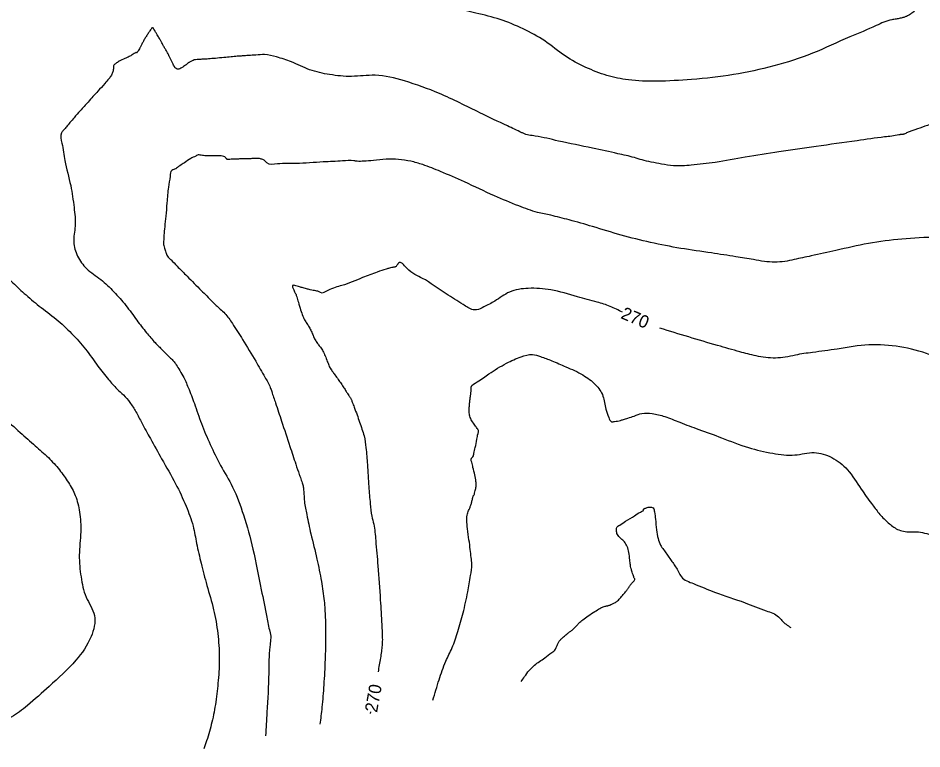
# Model space of a CAD drawing. Extents: x -475575 to -473225, y -1116053 to -1114104.
# Drawn here: x -474761.3 to -474473.3, y -1116036.6 to -1115803.6 of the extents above; entities that cross this region are included whole.
import ezdxf

# ---------------------------------------------------------------- set-up
doc = ezdxf.new("R2010")
doc.units = 0
for name, color, linetype in [('Vrstevnice_hlavni', 7, 'Continuous'), ('Vrstevnice_popis', 7, 'Continuous'), ('Vrstevnice_vedlejsi', 7, 'Continuous')]:
    doc.layers.add(name, color=color, linetype=linetype)

msp = doc.modelspace()

# ---------------------------------------------------------------- linework, layer by layer
at = {"layer": 'Vrstevnice_hlavni'}
msp.add_line((-474648.99, -1116025.33), (-474648.89, -1116024.79), dxfattribs=at)
for points in [[(-474568.71, -1115897.41), (-474572.64, -1115895.54), (-474576.77, -1115894.2), (-474583.07, -1115892.45), (-474591.54, -1115890.28), (-474598.74, -1115889.8), (-474604.7, -1115890.98), (-474609.4, -1115893.85), (-474612.89, -1115895.74), (-474615.18, -1115896.66), (-474616.27, -1115896.61), (-474619.51, -1115894.92), (-474624.89, -1115891.58), (-474632.42, -1115886.61), (-474637.48, -1115883.33), (-474640.07, -1115881.74), (-474640.18, -1115881.86), (-474640.33, -1115882.05), (-474640.51, -1115882.31), (-474640.73, -1115882.66), (-474640.99, -1115882.9), (-474641.29, -1115883.04), (-474641.64, -1115883.07), (-474642.2, -1115883.18), (-474642.99, -1115883.37), (-474643.99, -1115883.63), (-474646.84, -1115884.63), (-474651.55, -1115886.39), (-474658.1, -1115888.89), (-474662.58, -1115890.48), (-474664.99, -1115891.16), (-474665.32, -1115890.92), (-474665.81, -1115890.73), (-474666.45, -1115890.57), (-474667.26, -1115890.45), (-474668.24, -1115890.25), (-474669.42, -1115889.95), (-474670.78, -1115889.57), (-474671.91, -1115889.24), (-474672.82, -1115888.98), (-474673.5, -1115888.79), (-474673.83, -1115888.94), (-474673.83, -1115889.44), (-474673.49, -1115890.29), (-474673.21, -1115890.94), (-474673, -1115891.37), (-474672.85, -1115891.59), (-474672.51, -1115892.55), (-474671.99, -1115894.24), (-474671.28, -1115896.67), (-474670.56, -1115898.65), (-474669.83, -1115900.18), (-474669.09, -1115901.27), (-474668.39, -1115902.47), (-474667.74, -1115903.78), (-474667.12, -1115905.21), (-474666.45, -1115906.49), (-474665.72, -1115907.61), (-474664.93, -1115908.58), (-474664.18, -1115909.82), (-474663.46, -1115911.32), (-474662.77, -1115913.09), (-474662.29, -1115914.31), (-474662.01, -1115914.99), (-474661.93, -1115915.12), (-474661.85, -1115915.24), (-474661.77, -1115915.36), (-474661.68, -1115915.48), (-474661.29, -1115916.04), (-474660.58, -1115917.04), (-474659.56, -1115918.47), (-474658.61, -1115919.84), (-474657.73, -1115921.15), (-474656.92, -1115922.39), (-474656.31, -1115923.34), (-474655.89, -1115923.98), (-474655.67, -1115924.32), (-474655.48, -1115924.61), (-474655.32, -1115924.87), (-474655.2, -1115925.09), (-474654.82, -1115926.04), (-474654.19, -1115927.71), (-474653.3, -1115930.11), (-474652.48, -1115932.43), (-474651.74, -1115934.66), (-474651.05, -1115936.81), (-474650.47, -1115940.58), (-474649.97, -1115945.97), (-474649.57, -1115952.99), (-474649.1, -1115958.48), (-474648.57, -1115962.46), (-474647.98, -1115964.93), (-474647.34, -1115970.19), (-474646.64, -1115978.26), (-474645.89, -1115989.13), (-474645.42, -1115996.98), (-474645.23, -1116001.81)], [(-474353.29, -1115910.1), (-474357.76, -1115907), (-474363.58, -1115903.14), (-474372.98, -1115896.97), (-474385.95, -1115888.48), (-474394.72, -1115882.73), (-474399.29, -1115879.71), (-474399.64, -1115879.42), (-474399.97, -1115879.33), (-474400.27, -1115879.42), (-474400.55, -1115879.71), (-474401.05, -1115880.31), (-474401.76, -1115881.21), (-474402.7, -1115882.42), (-474405.92, -1115887.27), (-474411.43, -1115895.76), (-474419.22, -1115907.88), (-474425.86, -1115917.02), (-474431.34, -1115923.19), (-474435.67, -1115926.38), (-474439.9, -1115927.44), (-474444.04, -1115926.38), (-474448.08, -1115923.19), (-474453.87, -1115919.56), (-474461.41, -1115915.5), (-474470.71, -1115911.01), (-474480.28, -1115908.45), (-474490.15, -1115907.82), (-474500.29, -1115909.13), (-474508.12, -1115910.22), (-474513.62, -1115911.09), (-474516.81, -1115911.75), (-474519.96, -1115912.01), (-474523.07, -1115911.86), (-474526.15, -1115911.32), (-474531.26, -1115910.04), (-474538.41, -1115908.02), (-474556.79, -1115902.51)], [(-474816.35, -1115882.48), (-474812.34, -1115887.72), (-474809.86, -1115890.2), (-474806.89, -1115892.53), (-474803.45, -1115894.72), (-474798.76, -1115898.74), (-474792.83, -1115904.6), (-474785.65, -1115912.3), (-474778.81, -1115919.24), (-474772.32, -1115925.42), (-474766.16, -1115930.84), (-474760.66, -1115935.7), (-474755.83, -1115940.01), (-474751.67, -1115943.76), (-474748.15, -1115947.64), (-474745.29, -1115951.67), (-474743.07, -1115955.83), (-474741.75, -1115961.09), (-474741.33, -1115967.43), (-474741.81, -1115974.86), (-474741.25, -1115981.78), (-474739.64, -1115988.19), (-474736.98, -1115994.1), (-474738.06, -1116000.82), (-474742.88, -1116008.35), (-474751.44, -1116016.7), (-474758.32, -1116022.75), (-474763.52, -1116026.51), (-474767.05, -1116027.97), (-474772.66, -1116029.12), (-474780.38, -1116029.97), (-474790.19, -1116030.5), (-474798.72, -1116030.5), (-474805.98, -1116029.95), (-474817.95, -1116027.77)], [(-474645.23, -1116001.81), (-474645.33, -1116003.61), (-474645.52, -1116005.55), (-474645.82, -1116007.62), (-474646.61, -1116012.03)]]:
    msp.add_spline(points, degree=3, dxfattribs=at)
at = {"layer": 'Vrstevnice_vedlejsi'}
for points in [[(-474307.19, -1115713.78), (-474307.99, -1115713.91), (-474308.82, -1115714.23), (-474309.67, -1115714.76), (-474310.56, -1115715.49), (-474311.65, -1115716.4), (-474312.94, -1115717.49), (-474314.45, -1115718.76), (-474316.08, -1115719.99), (-474317.84, -1115721.19), (-474319.72, -1115722.34), (-474321.15, -1115723.17), (-474322.12, -1115723.66), (-474322.64, -1115723.82), (-474323.08, -1115724.06), (-474323.44, -1115724.38), (-474323.73, -1115724.79), (-474326.4, -1115725.43), (-474331.46, -1115726.31), (-474338.91, -1115727.42), (-474345.39, -1115728.27), (-474350.9, -1115728.88), (-474355.45, -1115729.23), (-474360.11, -1115731.22), (-474364.87, -1115734.85), (-474369.73, -1115740.13), (-474374.74, -1115745.26), (-474379.87, -1115750.27), (-474385.15, -1115755.13), (-474389.04, -1115759.06), (-474391.56, -1115762.05), (-474392.7, -1115764.11), (-474394.14, -1115766.16), (-474395.89, -1115768.21), (-474397.95, -1115770.27), (-474400.91, -1115771.86), (-474404.79, -1115773), (-474409.58, -1115773.69), (-474415.62, -1115774.92), (-474422.91, -1115776.7), (-474431.46, -1115779.03), (-474438.67, -1115781.14), (-474444.56, -1115783.02), (-474449.11, -1115784.67), (-474454.43, -1115787.3), (-474460.5, -1115790.89), (-474467.34, -1115795.44), (-474472.23, -1115798.79), (-474475.19, -1115800.92), (-474476.22, -1115801.84), (-474477.2, -1115802.56), (-474478.16, -1115803.09), (-474479.08, -1115803.42), (-474480.18, -1115803.71), (-474481.46, -1115803.96), (-474482.91, -1115804.16), (-474487.84, -1115806.05), (-474496.25, -1115809.62), (-474508.12, -1115814.87), (-474520.49, -1115818.88), (-474533.33, -1115821.66), (-474546.67, -1115823.22), (-474557.83, -1115823.77), (-474566.83, -1115823.34), (-474573.65, -1115821.91), (-474580.37, -1115819.36), (-474586.99, -1115815.71), (-474593.49, -1115810.94), (-474600.4, -1115807.07), (-474607.71, -1115804.11), (-474615.41, -1115802.05), (-474622.42, -1115800.42), (-474628.74, -1115799.21), (-474634.37, -1115798.42), (-474641.58, -1115797.17), (-474650.36, -1115795.45), (-474660.72, -1115793.27), (-474668.62, -1115791.35), (-474674.06, -1115789.69), (-474677.03, -1115788.3), (-474679.71, -1115787.15), (-474682.1, -1115786.24), (-474684.19, -1115785.57), (-474688.05, -1115785), (-474693.67, -1115784.55), (-474701.05, -1115784.19), (-474706.07, -1115783.9), (-474708.75, -1115783.67), (-474709.08, -1115783.5), (-474709.77, -1115783.43), (-474710.83, -1115783.48), (-474712.26, -1115783.64), (-474713.28, -1115783.74), (-474713.9, -1115783.78), (-474714.11, -1115783.76), (-474714.62, -1115783.69), (-474715.41, -1115783.58)], [(-474715.41, -1115783.58), (-474716.49, -1115783.41), (-474717.41, -1115783.5), (-474718.14, -1115783.85), (-474718.71, -1115784.44), (-474719.15, -1115784.82), (-474719.46, -1115785), (-474719.65, -1115784.96), (-474719.8, -1115784.94), (-474719.92, -1115784.95), (-474720.01, -1115784.96), (-474720.27, -1115784.88), (-474720.71, -1115784.68), (-474721.32, -1115784.37), (-474721.74, -1115784.16), (-474721.98, -1115784.03), (-474722.03, -1115784), (-474722.26, -1115783.79), (-474722.65, -1115783.41), (-474723.23, -1115782.87), (-474723.79, -1115782.38), (-474724.35, -1115781.96), (-474724.91, -1115781.61), (-474725.56, -1115781.21), (-474726.29, -1115780.75), (-474727.12, -1115780.24), (-474727.81, -1115779.87), (-474728.35, -1115779.63), (-474728.75, -1115779.52), (-474729.11, -1115779.37), (-474729.42, -1115779.18), (-474729.68, -1115778.96), (-474731.07, -1115778.77), (-474733.6, -1115778.64), (-474737.26, -1115778.54), (-474739.72, -1115778.49), (-474740.98, -1115778.46), (-474741.04, -1115778.47), (-474741.19, -1115778.56), (-474741.43, -1115778.72), (-474741.75, -1115778.95), (-474742.37, -1115779.43), (-474743.3, -1115780.14), (-474744.52, -1115781.08), (-474745.36, -1115781.72), (-474745.81, -1115782.05), (-474745.88, -1115782.08), (-474746.01, -1115782.13), (-474746.2, -1115782.23), (-474746.47, -1115782.35), (-474746.75, -1115782.51), (-474747.05, -1115782.7), (-474747.38, -1115782.92), (-474747.63, -1115783.11), (-474747.81, -1115783.27), (-474747.93, -1115783.4), (-474748.18, -1115783.65), (-474748.57, -1115784.01), (-474749.1, -1115784.5), (-474750.45, -1115785.52), (-474752.63, -1115787.06), (-474755.64, -1115789.12), (-474758.07, -1115790.75), (-474759.93, -1115791.95), (-474761.22, -1115792.71), (-474762.44, -1115793.47), (-474763.57, -1115794.23), (-474764.63, -1115794.98), (-474765.46, -1115795.73), (-474766.08, -1115796.48), (-474766.47, -1115797.22), (-474766.75, -1115797.84), (-474766.92, -1115798.31), (-474766.97, -1115798.65), (-474768.41, -1115800.47), (-474771.24, -1115803.78), (-474775.45, -1115808.57), (-474777.97, -1115814.72), (-474778.81, -1115822.24), (-474777.95, -1115831.12), (-474776.97, -1115840), (-474775.86, -1115848.87), (-474774.62, -1115857.75), (-474773.48, -1115865.15), (-474772.43, -1115871.08), (-474771.48, -1115875.54), (-474769.68, -1115879.76), (-474767.02, -1115883.75), (-474763.51, -1115887.5), (-474759.37, -1115891.39), (-474754.59, -1115895.43), (-474749.19, -1115899.61), (-474744.26, -1115904.19), (-474739.82, -1115909.19), (-474735.85, -1115914.59), (-474732.52, -1115918.82), (-474729.8, -1115921.88)], [(-474718.11, -1115807.08), (-474718.26, -1115806.78), (-474718.45, -1115806.69), (-474718.66, -1115806.8), (-474718.91, -1115807.13), (-474719.3, -1115807.69), (-474719.82, -1115808.47), (-474720.48, -1115809.49), (-474721.08, -1115810.48), (-474721.61, -1115811.44), (-474722.08, -1115812.38), (-474722.5, -1115813.17), (-474722.85, -1115813.8), (-474723.15, -1115814.29), (-474723.38, -1115814.59), (-474723.56, -1115814.7), (-474723.66, -1115814.62), (-474723.93, -1115814.7), (-474724.34, -1115814.94), (-474724.92, -1115815.34), (-474725.9, -1115815.89), (-474727.29, -1115816.58), (-474729.08, -1115817.41), (-474730.28, -1115818.18), (-474730.89, -1115818.88), (-474730.89, -1115819.53), (-474730.96, -1115820.14), (-474731.1, -1115820.73), (-474731.3, -1115821.28), (-474731.57, -1115821.84), (-474731.92, -1115822.41), (-474732.34, -1115822.97), (-474733.66, -1115824.49), (-474735.88, -1115826.97), (-474739.01, -1115830.4), (-474741.54, -1115833.21), (-474743.47, -1115835.4), (-474744.79, -1115836.97), (-474745.91, -1115838.3), (-474746.81, -1115839.4), (-474747.5, -1115840.26), (-474747.35, -1115843.49), (-474746.37, -1115849.09), (-474744.55, -1115857.06), (-474743.48, -1115864.03), (-474743.15, -1115870.02), (-474743.58, -1115875.01), (-474742.36, -1115879.5), (-474739.49, -1115883.49), (-474734.98, -1115886.97), (-474730.8, -1115890.89), (-474726.97, -1115895.22), (-474723.49, -1115899.97), (-474720.38, -1115903.94), (-474717.65, -1115907.1), (-474715.3, -1115909.48), (-474713.57, -1115911.21), (-474712.46, -1115912.3), (-474711.97, -1115912.75), (-474711.19, -1115913.8), (-474710.12, -1115915.46), (-474708.76, -1115917.73), (-474707.1, -1115921.4), (-474705.14, -1115926.46), (-474702.88, -1115932.92), (-474700.09, -1115939.52), (-474696.77, -1115946.25), (-474692.93, -1115953.13), (-474689.49, -1115962.02), (-474686.46, -1115972.93), (-474683.82, -1115985.87), (-474682.03, -1115994.63), (-474681.08, -1115999.2), (-474680.97, -1115999.6), (-474681.09, -1116004.02), (-474681.44, -1116012.47), (-474682.01, -1116024.94), (-474682.42, -1116032.42)], [(-474405.5, -1115810.13), (-474411, -1115813.31), (-474417.27, -1115815.95), (-474424.33, -1115818.06), (-474432.16, -1115819.63), (-474438.49, -1115821.66), (-474443.3, -1115824.16), (-474446.6, -1115827.13), (-474451.88, -1115830.21), (-474459.13, -1115833.4), (-474468.37, -1115836.7), (-474474.71, -1115838.99), (-474478.15, -1115840.26), (-474478.69, -1115840.51), (-474479.13, -1115840.68), (-474479.49, -1115840.76), (-474479.74, -1115840.75), (-474480.02, -1115840.77), (-474480.32, -1115840.82), (-474480.64, -1115840.89), (-474485.19, -1115841.53), (-474493.97, -1115842.75), (-474506.98, -1115844.55), (-474518.85, -1115846.29), (-474529.57, -1115847.99), (-474539.14, -1115849.64), (-474546.77, -1115850.55), (-474552.47, -1115850.73), (-474556.24, -1115850.16), (-474559.57, -1115849.54), (-474562.46, -1115848.86), (-474564.92, -1115848.12), (-474570.19, -1115846.87), (-474578.25, -1115845.11), (-474589.13, -1115842.83), (-474596.51, -1115841.25), (-474600.4, -1115840.37), (-474600.8, -1115840.18), (-474605.37, -1115838.01), (-474614.13, -1115833.84), (-474627.06, -1115827.68), (-474638.2, -1115823.69), (-474647.53, -1115821.88), (-474655.06, -1115822.24), (-474662.02, -1115821.65), (-474668.4, -1115820.11), (-474674.2, -1115817.62), (-474678.98, -1115816.02), (-474682.75, -1115815.29), (-474685.51, -1115815.43), (-474687.88, -1115815.58), (-474689.86, -1115815.71), (-474691.46, -1115815.83), (-474693.42, -1115816), (-474695.74, -1115816.22), (-474698.43, -1115816.48), (-474700.65, -1115816.67), (-474702.41, -1115816.78), (-474703.71, -1115816.82), (-474704.75, -1115816.93), (-474705.55, -1115817.13), (-474706.1, -1115817.42), (-474706.5, -1115817.63), (-474706.77, -1115817.76), (-474706.9, -1115817.82), (-474707.07, -1115817.94), (-474707.29, -1115818.12), (-474707.55, -1115818.35), (-474707.99, -1115818.68), (-474708.63, -1115819.11), (-474709.46, -1115819.64), (-474710.11, -1115819.92), (-474710.58, -1115819.96), (-474710.88, -1115819.74), (-474711.12, -1115819.56), (-474711.3, -1115819.42), (-474711.41, -1115819.3), (-474711.61, -1115818.94), (-474711.92, -1115818.33), (-474712.31, -1115817.48), (-474712.71, -1115816.64), (-474713.12, -1115815.83), (-474713.53, -1115815.03), (-474713.9, -1115814.35), (-474714.23, -1115813.79), (-474714.53, -1115813.33), (-474714.81, -1115812.86), (-474715.06, -1115812.38), (-474715.28, -1115811.88), (-474715.67, -1115811.15), (-474716.23, -1115810.18), (-474716.96, -1115808.98), (-474717.48, -1115808.13), (-474717.78, -1115807.64), (-474717.86, -1115807.51), (-474717.97, -1115807.32), (-474718.11, -1115807.08)], [(-474209.03, -1115951.03), (-474211.31, -1115950.17), (-474219.22, -1115947.13), (-474229.61, -1115943.09), (-474237.42, -1115939.16), (-474242.66, -1115935.36), (-474245.32, -1115931.66), (-474248.92, -1115928.32), (-474253.48, -1115925.32), (-474258.98, -1115922.66), (-474263.71, -1115920.22), (-474267.65, -1115917.99), (-474270.81, -1115915.98), (-474273.58, -1115914.5), (-474275.98, -1115913.57), (-474277.99, -1115913.16), (-474281.05, -1115911.98), (-474285.17, -1115910), (-474290.34, -1115907.25), (-474296.51, -1115904.05), (-474303.67, -1115900.41), (-474311.84, -1115896.33), (-474318.14, -1115893.11), (-474322.6, -1115890.76), (-474325.19, -1115889.28), (-474328.18, -1115887.42), (-474331.54, -1115885.19), (-474335.3, -1115882.6), (-474339.21, -1115879.95), (-474343.3, -1115877.27), (-474347.55, -1115874.53), (-474351.29, -1115870.13), (-474354.53, -1115864.06), (-474357.27, -1115856.31), (-474360.52, -1115850.2), (-474364.29, -1115845.71), (-474368.57, -1115842.86), (-474374.44, -1115840.32), (-474381.9, -1115838.09), (-474390.95, -1115836.19), (-474398.08, -1115835.56), (-474403.29, -1115836.19), (-474406.58, -1115838.09), (-474412.12, -1115842.87), (-474419.91, -1115850.52), (-474429.96, -1115861.04), (-474437.29, -1115868.36), (-474441.9, -1115872.47), (-474443.81, -1115873.38), (-474448.89, -1115873.86), (-474457.14, -1115873.93), (-474468.57, -1115873.57), (-474479.64, -1115874.09), (-474490.34, -1115875.48), (-474500.68, -1115877.74), (-474508.57, -1115879.45), (-474514.01, -1115880.62), (-474517.01, -1115881.23), (-474520.17, -1115881.44), (-474523.49, -1115881.23), (-474526.98, -1115880.62), (-474532.59, -1115879.71), (-474540.32, -1115878.52), (-474550.16, -1115877.05), (-474559.76, -1115875.15), (-474569.12, -1115872.83), (-474578.24, -1115870.1), (-474585.73, -1115867.98), (-474591.57, -1115866.48)], [(-474591.57, -1115866.48), (-474595.79, -1115865.6), (-474601.77, -1115863.53), (-474609.52, -1115860.29), (-474619.05, -1115855.86), (-474626.67, -1115852.55), (-474632.38, -1115850.36), (-474636.19, -1115849.29), (-474640.08, -1115848.71), (-474644.04, -1115848.63), (-474648.09, -1115849.05), (-474651.15, -1115849.27), (-474653.22, -1115849.3), (-474654.32, -1115849.13), (-474657.93, -1115849.19), (-474664.05, -1115849.49), (-474672.69, -1115850.01), (-474678.68, -1115850.13), (-474682.02, -1115849.83), (-474682.72, -1115849.12), (-474683.59, -1115848.65), (-474684.63, -1115848.42), (-474685.83, -1115848.44), (-474687.09, -1115848.46), (-474688.41, -1115848.49), (-474689.78, -1115848.53), (-474691.08, -1115848.57), (-474692.3, -1115848.61), (-474693.44, -1115848.66), (-474694.21, -1115848.68), (-474694.61, -1115848.7), (-474694.63, -1115848.7), (-474694.65, -1115848.69), (-474694.66, -1115848.69), (-474694.67, -1115848.68), (-474694.81, -1115848.54), (-474695.07, -1115848.28), (-474695.46, -1115847.89), (-474696.14, -1115847.64), (-474697.11, -1115847.54), (-474698.36, -1115847.58), (-474699.5, -1115847.6), (-474700.52, -1115847.58), (-474701.42, -1115847.54), (-474702.23, -1115847.47), (-474702.96, -1115847.38), (-474703.6, -1115847.26), (-474704.7, -1115847.62), (-474706.28, -1115848.45), (-474708.32, -1115849.77), (-474709.74, -1115850.69), (-474710.54, -1115851.23), (-474710.73, -1115851.39), (-474710.86, -1115851.5), (-474710.94, -1115851.58), (-474710.97, -1115851.62), (-474711.2, -1115851.74), (-474711.65, -1115851.93), (-474712.29, -1115852.2), (-474712.88, -1115854.06), (-474713.41, -1115857.53), (-474713.88, -1115862.59), (-474714.27, -1115866.83), (-474714.59, -1115870.23), (-474714.83, -1115872.82), (-474714.93, -1115874.8), (-474714.89, -1115876.18), (-474714.7, -1115876.96), (-474714.49, -1115877.67), (-474714.27, -1115878.32), (-474714.04, -1115878.91), (-474713.67, -1115879.51), (-474713.18, -1115880.13), (-474712.56, -1115880.75), (-474710.65, -1115882.69), (-474707.44, -1115885.94), (-474702.93, -1115890.49), (-474699.42, -1115893.98), (-474696.92, -1115896.42), (-474695.42, -1115897.79), (-474693.03, -1115901.02), (-474689.76, -1115906.11), (-474685.59, -1115913.05), (-474682.66, -1115918.14), (-474680.95, -1115921.36), (-474680.48, -1115922.72), (-474679.28, -1115926.31), (-474677.35, -1115932.12), (-474674.7, -1115940.16), (-474672.82, -1115945.83), (-474671.7, -1115949.14), (-474671.35, -1115950.09), (-474671.05, -1115950.95), (-474670.78, -1115951.74), (-474670.56, -1115952.44), (-474670.37, -1115953.67), (-474670.21, -1115955.42)], [(-474629.16, -1116021.12), (-474627.14, -1116014.55), (-474625, -1116008.66), (-474623, -1116004.33), (-474621.17, -1115999.2), (-474619.51, -1115993.27), (-474618.02, -1115986.54), (-474617.09, -1115981.36), (-474616.72, -1115977.71), (-474616.91, -1115975.61), (-474617.21, -1115973.04), (-474617.62, -1115969.98), (-474618.13, -1115966.44), (-474618.29, -1115963.66), (-474618.11, -1115961.63), (-474617.59, -1115960.34), (-474617.2, -1115959.33), (-474616.94, -1115958.59), (-474616.81, -1115958.12), (-474616.68, -1115957.61), (-474616.55, -1115957.06), (-474616.41, -1115956.46), (-474616.27, -1115956.03), (-474616.14, -1115955.75), (-474616.01, -1115955.62), (-474615.83, -1115955.12), (-474615.62, -1115954.23), (-474615.37, -1115952.97), (-474615.4, -1115951.32), (-474615.73, -1115949.29), (-474616.35, -1115946.88), (-474616.75, -1115945.22), (-474616.92, -1115944.31), (-474616.88, -1115944.14), (-474616.77, -1115943.95), (-474616.6, -1115943.72), (-474616.36, -1115943.46), (-474616.03, -1115942.4), (-474615.6, -1115940.55), (-474615.07, -1115937.91), (-474614.73, -1115936.11), (-474614.6, -1115935.14), (-474614.67, -1115935.01), (-474615.04, -1115934.44), (-474615.72, -1115933.45), (-474616.7, -1115932.02), (-474617.32, -1115930.59), (-474617.6, -1115929.14), (-474617.52, -1115927.68), (-474617.42, -1115926.35), (-474617.28, -1115925.14), (-474617.11, -1115924.05), (-474616.99, -1115923.05), (-474616.92, -1115922.15), (-474616.91, -1115921.33), (-474615.02, -1115919.64), (-474611.26, -1115917.08), (-474605.63, -1115913.66), (-474601.01, -1115911.59), (-474597.41, -1115910.89), (-474594.81, -1115911.55), (-474591.26, -1115912.86), (-474586.75, -1115914.81), (-474581.29, -1115917.41), (-474577.35, -1115920.51), (-474574.92, -1115924.14), (-474574.01, -1115928.27), (-474573.09, -1115931), (-474572.16, -1115932.33), (-474571.21, -1115932.24), (-474570.27, -1115932.09), (-474569.34, -1115931.88)], [(-474729.8, -1115921.88), (-474727.72, -1115923.75), (-474725.7, -1115926.18), (-474723.75, -1115929.16), (-474721.88, -1115932.69), (-474719.15, -1115937.68), (-474715.56, -1115944.14), (-474711.13, -1115952.07), (-474707.8, -1115959.21), (-474705.56, -1115965.57), (-474704.43, -1115971.13), (-474702.96, -1115977.43), (-474701.15, -1115984.47), (-474699, -1115992.23), (-474697.68, -1115999.87), (-474697.19, -1116007.38), (-474697.53, -1116014.75), (-474698.32, -1116021.66), (-474699.55, -1116028.09), (-474701.24, -1116034.04), (-474702.17, -1116036.61)], [(-474569.34, -1115931.88), (-474568.42, -1115931.59), (-474566.98, -1115931.13), (-474565, -1115930.49), (-474562.5, -1115929.67), (-474559.24, -1115929.73), (-474555.23, -1115930.67), (-474550.45, -1115932.5), (-474544.42, -1115934.75), (-474537.12, -1115937.43), (-474528.56, -1115940.55), (-474520.79, -1115942.37), (-474513.8, -1115942.91), (-474507.6, -1115942.16), (-474502.01, -1115943.72), (-474497.03, -1115947.6), (-474492.66, -1115953.8), (-474489.31, -1115958.42), (-474486.99, -1115961.47), (-474485.69, -1115962.93), (-474484.34, -1115964.24), (-474482.93, -1115965.4), (-474481.47, -1115966.41), (-474479.67, -1115967.07), (-474477.53, -1115967.41), (-474475.06, -1115967.41), (-474469.79, -1115968.48), (-474461.73, -1115970.63), (-474450.86, -1115973.85), (-474440.49, -1115975.41), (-474430.62, -1115975.33), (-474421.24, -1115973.59), (-474413.66, -1115972.82), (-474407.9, -1115973.02), (-474403.95, -1115974.18), (-474399.42, -1115975.28)], [(-474670.21, -1115955.42), (-474670.07, -1115957.71), (-474669.34, -1115961.92), (-474668.01, -1115968.05), (-474666.08, -1115976.1), (-474664.67, -1115983.23), (-474663.78, -1115989.43), (-474663.42, -1115994.72), (-474663.31, -1116000.94), (-474663.47, -1116008.1), (-474663.89, -1116016.21), (-474664.48, -1116023.35), (-474665.14, -1116028.76)], [(-474570.59, -1115966.38), (-474570.55, -1115966.04), (-474569.59, -1115965.25), (-474567.7, -1115964), (-474564.88, -1115962.29), (-474563, -1115961.1), (-474562.05, -1115960.44), (-474562.03, -1115960.3), (-474561.97, -1115960.18), (-474561.86, -1115960.08), (-474561.72, -1115960), (-474561.45, -1115959.89), (-474561.05, -1115959.75), (-474560.53, -1115959.58), (-474560, -1115959.53), (-474559.48, -1115959.6), (-474558.96, -1115959.8), (-474558.52, -1115961.07), (-474558.17, -1115963.39), (-474557.89, -1115966.79), (-474557.37, -1115969.54), (-474556.61, -1115971.64), (-474555.6, -1115973.09), (-474554.61, -1115974.49), (-474553.64, -1115975.86), (-474552.7, -1115977.19), (-474551.76, -1115978.61), (-474550.83, -1115980.13), (-474549.91, -1115981.74), (-474546.08, -1115983.92), (-474539.33, -1115986.67), (-474529.66, -1115989.99), (-474522.87, -1115992.6), (-474518.96, -1115994.5), (-474517.91, -1115995.68), (-474515.08, -1115997.91)], [(-474600.96, -1116015.14), (-474599.89, -1116013.55), (-474596.75, -1116009.91), (-474593.5, -1116007.61), (-474591.26, -1116005.91), (-474590.03, -1116004.81), (-474589.8, -1116004.32), (-474589.59, -1116003.84), (-474589.4, -1116003.36), (-474589.23, -1116002.9), (-474588.99, -1116002.46), (-474588.68, -1116002.05), (-474588.31, -1116001.67), (-474587.9, -1116001.28), (-474587.46, -1116000.88), (-474586.99, -1116000.47), (-474586.42, -1116000), (-474585.75, -1115999.48), (-474584.98, -1115998.9), (-474584.19, -1115998.22), (-474583.39, -1115997.42), (-474582.57, -1115996.51), (-474581.32, -1115995.44), (-474579.63, -1115994.21), (-474577.51, -1115992.81), (-474575.9, -1115991.84), (-474574.81, -1115991.28), (-474574.23, -1115991.14), (-474573.76, -1115991.03), (-474573.4, -1115990.96), (-474573.15, -1115990.91), (-474572.71, -1115990.75), (-474572.06, -1115990.48), (-474571.21, -1115990.08), (-474570.28, -1115989.38), (-474569.28, -1115988.38), (-474568.19, -1115987.08), (-474567.38, -1115986.07), (-474566.85, -1115985.35), (-474566.6, -1115984.93), (-474566.37, -1115984.58), (-474566.17, -1115984.29), (-474565.98, -1115984.06), (-474565.71, -1115983.77), (-474565.37, -1115983.41), (-474564.96, -1115982.98), (-474564.75, -1115982.62), (-474564.74, -1115982.35), (-474564.93, -1115982.15), (-474565.14, -1115981.74), (-474565.35, -1115981.12), (-474565.59, -1115980.27), (-474565.78, -1115979.63), (-474565.93, -1115979.18), (-474566.04, -1115978.93), (-474566.2, -1115977.98), (-474566.4, -1115976.34), (-474566.66, -1115974), (-474567.22, -1115972.09), (-474568.07, -1115970.6), (-474569.24, -1115969.54), (-474570.04, -1115968.63), (-474570.48, -1115967.89), (-474570.56, -1115967.3), (-474570.6, -1115966.8), (-474570.59, -1115966.38)]]:
    msp.add_spline(points, degree=3, dxfattribs=at)

# ---------------------------------------------------------------- texts
at = {"layer": 'Vrstevnice_popis'}
for rotation, p in [(336.8301, (-474570.89, -1115898.65)), (79.8457, (-474647.19, -1116026.64))]:
    msp.add_text(' 270 ', height=4, rotation=rotation, dxfattribs=at).set_placement(p)

doc.saveas('drawing.dxf')
